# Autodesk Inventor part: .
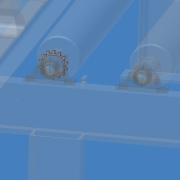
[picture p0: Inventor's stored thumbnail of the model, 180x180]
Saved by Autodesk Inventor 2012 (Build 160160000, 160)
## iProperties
Shininess: 20.0
Length Units: 11269
Angle Units: 11279
Time Units: 11290
Mass Units: 11283
Length Display Precision: 3
Angle Display Precision: 2
Company: CAD-Verlag
Created: 2001-02
Part Number: .
Material: Steel, Mild
Document SubType Name: Modeling
Description: Kettentyp 12 B.
Density: 7.86 g/cm^3
Density: 7.860000000000001
Volumn: 4.275153872104327
Area: 21.350802561518744
PropertySet Name: Model Information
Control State: 0
Master: False
Checked Out: False
TAB_typ: 12 B
TAB_d1: 12.07
TAB_t: 19.05
TAB_z0: 14
TAB_z1: 15
TAB_dd0: 85.61
TAB_dd1: 91.625
TAB_dd2: 0
TAB_dd3: 0
TAB_dfmin0: 73.54
TAB_dfmin1: 79.555
TAB_rimin: 6.095
TAB_remin0: 23.174
TAB_remin1: 24.623
TAB_alfamin0: 134
TAB_alfamin1: 134
+MSCProtocol1+ProtocolID: P00040914100554197
+MSCProtocol2+Protocol: P00040914100554197<@PID>[Version]<@EL>Version=2.2<@EL>[Files]<@EL>DataFile=SpiData|N023311<@EL>[CalcData]<@EL>IsMCW=0<@EL>[Synchronize]<@EL>ChangedVars=<@EL>[Ca
Author: Jürgen Kronas
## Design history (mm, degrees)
extrude "ExtrusionBlind1" new body distance "d3" = 19.46 (= msp_b); taper "d4" = 0 deg
  node "Sketch1" dims "d2" = 90.413 (= msp_d0)
sketch "Sketch4"
  geometry: A1 r 16.762 centre (0, 0) between (-16.62, -2.182) and (-15.921, -5.245) reference
hole "Hole1" sketch "Sketch4" diameter "d26" = 14.735 (= hole); stored, may be unused: countersink angle "d30" = 60 deg, drill point angle "d32" = 118 deg; dims "d27" = 6, "d28" = 4, "d29" = 2, "d31" = 8
sketch "Sketch5"
  geometry: L1 (0, -9.002)-(0, 20.171) reference; L2 (-45.206, 0)-(-45.206, 5.872); L3 (-45.206, 5.872)-(-36.77, 4.182); L4 (-36.77, 4.182)-(-29.47, 4.182); L5 (-29.47, 4.182)-(-29.47, 0); L6 (-29.47, 0)-(-29.47, -4.182); L7 (-29.47, -4.182)-(-36.77, -4.182); L8 (-36.77, -4.182)-(-45.206, -5.872); L9 (-45.206, -5.872)-(-45.206, 0); L10 (-45.206, 0)-(45.206, 0) reference; L11 (-45.206, 0)-(-45.206, 19.46) reference; A1 r 9.391 centre (-37.878, 0) between (-45.206, 5.872) and (-29.47, 4.182)
  constraints: 16 end point, 4 equal length, 4 parallel, 3 point on circle, 2 collinear, 1 centre point, 1 perpendicular, 1 point on line
  dimensions: "d33" = 8.364 distance between parallel lines of L7 L4 (= prf_e - prf_bf1); "d35" = 1.6898 vertical distance of L2.end L3.end (= msp_ba); "d36" = 73.54 diameter of L7.end L1 (= msp_df); "d37" = 58.94 diameter of L6 L1 (= msp_dg)
revolve "Revolution2" sketch "Sketch5" stored, may be unused: angle "d38" = 90 deg
pattern_linear "Rectangular Pattern2" dims "d41" = 19.46 (= prf_e)
sketch "Sketch6"
  geometry: L1 (0, 26.82)-(0, -20.115) reference; L2 (-20.115, 0)-(26.82, 0) reference; L3 (-7.878, 44.515)-(-5.264, 39.853); L4 (5.264, 39.853)-(7.878, 44.515); A1 r 6.035 centre (0, 42.805) between (-5.264, 39.853) and (5.264, 39.853); A2 r 45.206 centre (0, 0) between (7.878, 44.515) and (-7.878, 44.515); A3 r 45.206 centre (0, 0) between (-7.878, 44.515) and (7.878, 44.515) reference
  constraints: 6 point on circle, 4 end point, 2 centre point, 2 point on line, 2 tangent, 1 concentric, 1 equal length
  dimensions: "d42" = 85.61 diameter of A1.centre L2 (= msp_d); "d43" = 12.07 diameter of A1 (= prf_d1); "d44" = 58.5714 deg angle of L4 L3 (= msp_alfa)
extrude "Extrusion3" cut sketch "Sketch6" stored distance "d45" = 10; taper "d46" = 0 deg
pattern_circular "Circular Pattern2" dims angle "d49" = 360 deg
sketch "Skizze7"
  geometry: C1 r 29.47 at (0, 0) reference; C2 r 32 at (0, 0)
  constraints: 1 centre point, 1 coincident
  dimensions: "d53" = 64 diameter of C2
extrude "Extrusion4" cut sketch "Skizze7" stored distance "d54" = 10; taper "d55" = 0 deg
node "Volumenkörper1"
node "Volumenkörpern"
node "Oberflächenkörpern"
other parameters: "prf_bf1" = 11.096 [user parameter; used in 1 equation term], "prf_d1" = 12.07 [user parameter; used in 2 equation terms], "prf_e" = 19.46 [user parameter; used in 2 equation terms], "prf_dd0" = 85.61 [user parameter; used in 1 equation term], "prf_damin0" = 90.413 [user parameter; used in 1 equation term], "prf_dgmax0" = 58.94 [user parameter; used in 1 equation term], "prf_bk" = 19.46 [user parameter; used in 1 equation term], "msp_ba" = 1.6898 (= 0.14 x prf_d1) [user parameter; used in 1 equation term], "msp_d" = 85.61 (= prf_dd0) [user parameter; used in 1 equation term], "prf_dfmin0" = 73.54 [user parameter; used in 1 equation term], "msp_da" = 90.413 (= prf_damin0) [user parameter; used in 1 equation term], "msp_dg" = 58.94 (= prf_dgmax0) [user parameter; used in 2 equation terms], "msp_b" = 19.46 (= prf_bk) [user parameter; used in 1 equation term], "msp_df" = 73.54 (= prf_dfmin0) [user parameter; used in 1 equation term], "msp_alfa" = 58.5714 deg (computed from msp_z) [user parameter; used in 1 equation term], "msp_d0" = 90.413 (= msp_da) [user parameter; used in 1 equation term], "hole" = 14.735 (= 0.25 x msp_dg) [user parameter; used in 1 equation term], "d1" = 33.525 (derived), "d5" = 0, "d6" = 1.1914 (derived), "d8" = 6.7125 (derived), "d17" = 11.71864 (derived), "d19" = 8.51 (derived), "d52" = 0
